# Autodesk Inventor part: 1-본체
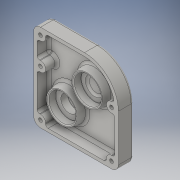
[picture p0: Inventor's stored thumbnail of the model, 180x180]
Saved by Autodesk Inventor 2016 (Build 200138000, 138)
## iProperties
Created: 2015-11
Part Number: 1-본체
Material: Generic
Document SubType Name: Modeling
Designer: Administrator
Density: 1 g/cm^3
Appearance: Default
Author: Administrator
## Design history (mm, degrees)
sketch "Sketch1"
  geometry: L1 (-30, 73)-(70, 73); L2 (70, 73)-(70, -30); L3 (70, -30)-(-30, -30); L4 (-30, -30)-(-30, 73); 1 further point
  constraints: 8 end point, 2 parallel, 1 horizontal, 1 perpendicular
  dimensions: "d0" = 100 distance of L2.end L3.end; "d1" = 103 distance of L3.end L1.start; "d2" = 30 distance from line of point (0, 0) L4; "d3" = 30 distance from line of point (0, 0) L3
extrude "Extrusion1" new body sketch "Sketch1" distance "d4" = 18; taper "d5" = 0 deg
fillet "Fillet1" dims "d6" = 40
shell "Shell1" dims "d7" = 4
sketch "Sketch2"
  geometry: L1 (-30, -30)-(70, -30) reference; L2 (-30, 73)-(-30, -30) reference; L3 (-22, 59)-(-26, 59); L4 (-26, -26)-(-26, 69) reference; L5 (-16, 65)-(-16, 69); L6 (-22, 39)-(-26, 39); L7 (-22, 27)-(-26, 27); L8 (-22, -16)-(-26, -16); L9 (-16, -22)-(-16, -26); L10 (66, -26)-(-26, -26) reference; L11 (62, 27)-(66, 27); L12 (62, 39)-(65.496, 39); L13 (56, -22)-(56, -26); L14 (62, -16)-(66, -16); L15 (66, 33)-(66, -26) reference; L16 (-26, 69)-(30, 69) reference; L17 (-26, 59)-(-26, 69); L18 (-16, 69)-(-26, 69); L19 (-26, 39)-(-26, 27); L20 (-26, -16)-(-26, -26); L21 (-16, -26)-(-26, -26); L22 (66, 33)-(66, -26) reference; L23 (66, 27)-(66, 33); L24 (66, -16)-(66, -26); L25 (66, -26)-(56, -26); A1 r 6 centre (-22, 65) between (-22, 59) and (-16, 65); A2 r 6 centre (-22, 33) between (-22, 27) and (-22, 39); A3 r 6 centre (-22, -22) between (-16, -22) and (-22, -16); A4 r 6 centre (62, 33) between (62, 39) and (62, 27); A5 r 6 centre (62, -22) between (62, -16) and (56, -22); A6 r 36 centre (30, 33) between (66, 33) and (30, 69) reference; A7 r 36 centre (30, 33) between (66, 33) and (65.496, 39); 1 further point
  constraints: 36 end point, 13 point on circle, 10 tangent, 8 collinear, 8 perpendicular, 7 point on line, 6 centre point, 5 equal radius, 3 vertical alignment, 2 horizontal, 2 horizontal alignment
  dimensions: "d9" = 12 diameter of A1; "d10" = 84 horizontal distance of A4.centre A1.centre; "d11" = 32 vertical distance of A4.centre A1.centre; "d12" = 55 distance of A5.centre A4.centre; "d13" = 8 distance from line of A5.centre L1; "d14" = 8 distance from line of L2 A1.centre
extrude "Extrusion2" join sketch "Sketch2" stored distance "d15" = 18; taper "d16" = 0 deg
fillet "Fillet2" dims "d17" = 8
sketch "Sketch4"
  geometry: A1 r 6 centre (-62, 33) between (-62, 27) and (-62, 39) reference; A2 r 6 centre (-62, -22) between (-56, -22) and (-62, -16) reference; A3 r 6 centre (22, 65) between (16, 65) and (22, 59) reference; A4 r 6 centre (22, 33) between (22, 39) and (22, 27) reference; A5 r 6 centre (22, -22) between (22, -16) and (16, -22) reference; 1 further point
hole "Hole1" sketch "Sketch4" at (-62, -22), (22, -22), (22, 33), (22, 65), (-62, 33) diameter "d18" = 4.5; stored, may be unused: countersink angle "d22" = 90 deg, drill point angle "d24" = 118 deg; dims "d19" = 6, "d20" = 8, "d21" = 4.4, "d23" = 8
sketch "Sketch6"
  geometry: C1 r 20 at (46, 59); C2 r 20 at (16, 26); A1 r 40 centre (46, 59) between (86, 59) and (46, 99) reference; 1 further point
  constraints: 2 centre point, 1 coincident, 1 concentric, 1 equal radius
  dimensions: "d27" = 40 diameter of C1
extrude "Extrusion3" join sketch "Sketch6" distance "d29" = 11; taper "d30" = -10 deg
hole "Hole2" diameter "d33" = 22; stored, may be unused: countersink angle "d37" = 90 deg, drill point angle "d39" = 0 deg; dims "d31" = 10, "d32" = 10, "d34" = 6, "d35" = 32, "d36" = 9, "d38" = 11
sketch "Sketch7"
  geometry: C1 r 25 at (0, 0); 1 further point
  constraints: 1 centre point, 1 coincident
  dimensions: "d40" = 50 diameter of C1
extrude "Extrusion4" join sketch "Sketch7" distance "d41" = 15; taper "d42" = -10 deg
hole "Hole3" diameter "d45" = 20; stored, may be unused: countersink angle "d49" = 90 deg, drill point angle "d51" = 0 deg; dims "d43" = 10, "d44" = 10, "d46" = 6, "d47" = 32, "d48" = 9, "d50" = 11
hole "Hole4" diameter "d54" = 24; stored, may be unused: countersink angle "d58" = 90 deg, drill point angle "d60" = 0 deg; dims "d52" = 10, "d53" = 10, "d55" = 6, "d56" = 28, "d57" = 11, "d59" = 13
sketch "Sketch8"
  geometry: L1 (-34.887, 56.602)-(14.887, 56.602); L2 (14.887, 56.602)-(14.887, 49.398); L3 (14.887, 49.398)-(-34.887, 49.398); L4 (-34.887, 49.398)-(-34.887, 56.602); L5 (30, -22)-(30, 65) reference; L6 (22, 73)-(-30, 73) reference; 4 further points
  constraints: 2 midpoint, 1 horizontal alignment, 1 vertical alignment, 2 other
  dimensions: "d61" = 40 distance from line of point (-10, 53) L5; "d62" = 20 distance from line of point (-10, 53) L6
emboss "Emboss1" sketch "Sketch8" dims "d0" = 100, "d1" = 103, "d2" = 30, "d3" = 30, "d63" = 0.5, "d64" = 0
sketch "Sketch9"
  geometry: 2 further points
  constraints: 1 vertical alignment
  dimensions: "d65" = 18 distance of point (0, 0) point (0, 18)
hole "Hole5" sketch "Sketch9" at (0, 18) diameter "d66" = 2.459; stored, may be unused: countersink angle "d70" = 90 deg, drill point angle "d72" = 118 deg; dims "d67" = 8, "d68" = 28, "d69" = 11, "d71" = 10
pattern_circular "Circular Pattern1" dims angle "d74" = 360 deg
fillet "Fillet3" dims "d76" = 0.3
chamfer "Chamfer1" distance "d77" = 1; stored, may be unused: second distance "d78" = 2, angle "d79" = 45 deg
fillet "Fillet4" dims "d80" = 3
fillet "Fillet5" dims "d81" = 3
fillet "Fillet6" dims "d82" = 3
fillet "Fillet7" dims "d83" = 3
body "Solid1"
